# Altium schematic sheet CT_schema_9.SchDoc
size 274 x 160 mm
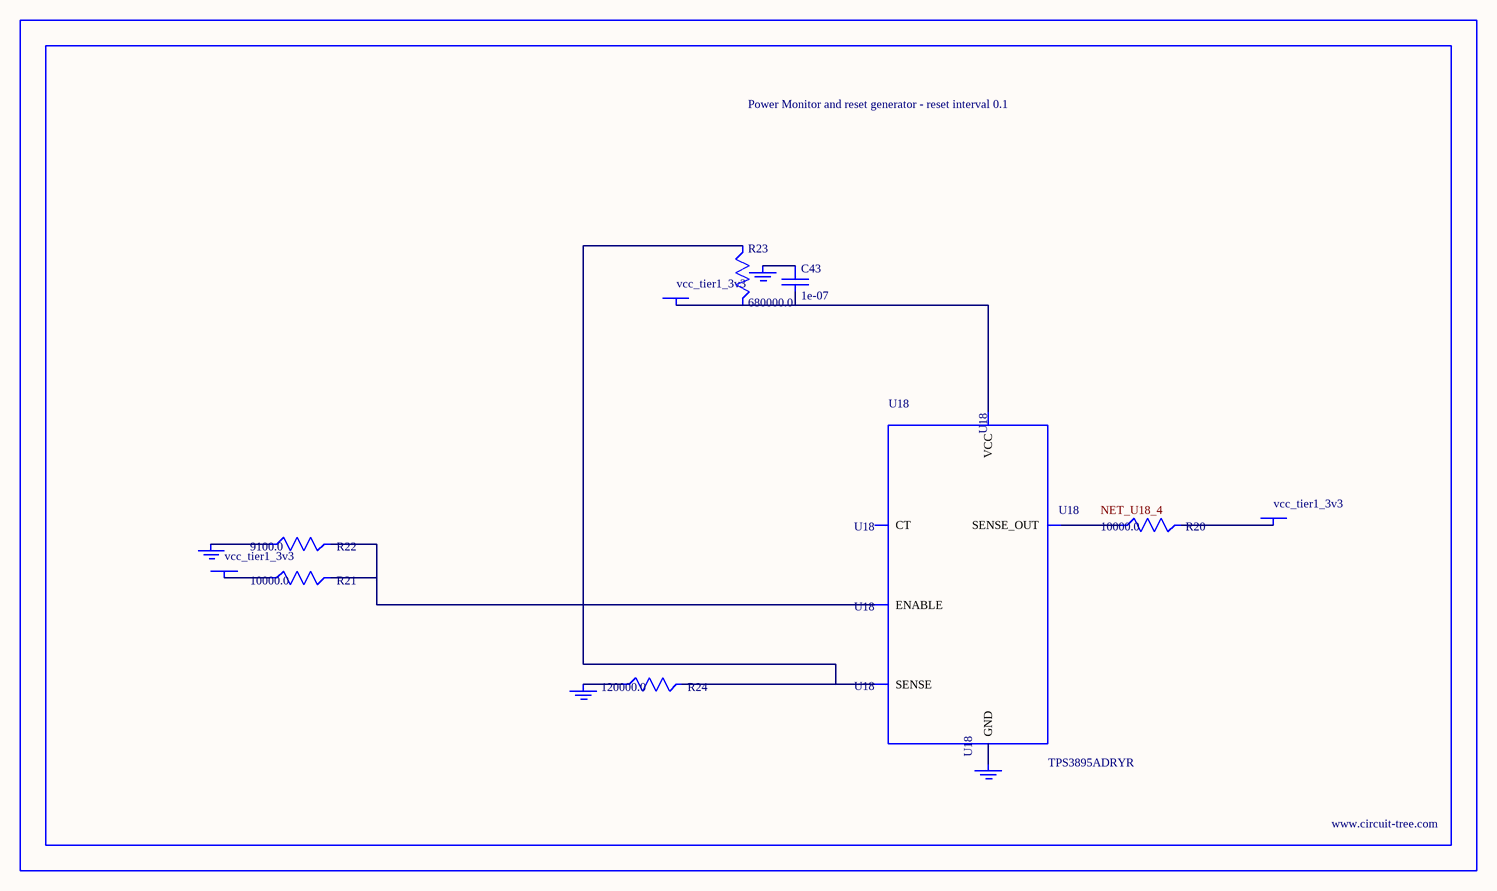
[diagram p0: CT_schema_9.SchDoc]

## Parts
BORDER8  (no value)
C43  1e-07  [C0402]
GND_INSTANCE_8_0  (no value)
GND_INSTANCE_8_1  (no value)
GND_INSTANCE_8_2  (no value)
GND_INSTANCE_8_3  (no value)
POWER_INSTANCE_8_0  vcc_tier1_3v3
POWER_INSTANCE_8_1  vcc_tier1_3v3
POWER_INSTANCE_8_2  vcc_tier1_3v3
R20  10000.0  [R0603]
R21  10000.0  [R0603]
R22  9100.0  [R0603]
R23  680000.0  [R0603]
R24  120000.0  [R0603]
U18  TPS3895ADRYR  [SON-6]

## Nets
NetC43_1: C43.1 GND_INSTANCE_8_2.0(GND)
NetC43_2: C43.2 POWER_INSTANCE_8_2.0(PWR) R23.2 U18.6(VCC)
NetGND_INSTANCE_8_0_0: GND_INSTANCE_8_0.0(GND) R22.1
NetGND_INSTANCE_8_1_0: GND_INSTANCE_8_1.0(GND) R24.1
NetGND_INSTANCE_8_3_0: GND_INSTANCE_8_3.0(GND) U18.2(GND)
NetPOWER_INSTANCE_8_0_0: POWER_INSTANCE_8_0.0(PWR) R21.1
NetPOWER_INSTANCE_8_1_0: POWER_INSTANCE_8_1.0(PWR) R20.2
NetR20_1: R20.1 U18.4(SENSE_OUT)
NetR21_2: R21.2 R22.2 U18.1(ENABLE)
NetR23_1: R23.1 R24.2 U18.3(SENSE)

Not connected (* = marked no-connect by the designer): U18 5(CT)

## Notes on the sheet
- Labels drawn without touching a wire or pin: NET_U18_4

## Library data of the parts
BORDER8 = BORDER_PAGE8
C43 = C0402C104K3RACTU
GND_INSTANCE_8_0-GND_INSTANCE_8_3 = GND
POWER_INSTANCE_8_0-POWER_INSTANCE_8_2 = PWR
R20 R21 = RC0603JR-0710KL
R22 = RC0603JR-079K1L
R23 = RC0603JR-07680KL
R24 = RC0603JR-07120KL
